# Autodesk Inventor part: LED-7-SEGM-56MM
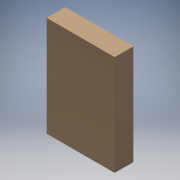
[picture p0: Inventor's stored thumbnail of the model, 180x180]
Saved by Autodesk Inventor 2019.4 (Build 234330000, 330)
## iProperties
Created: 2019-11
Part Number: LED-7-SEGM-56MM
Material: Generic
Document SubType Name: Modeling
Designer: Willist
Density: 1 g/cm^3
Appearance: MYTHT, LED-7-SEGM-56MM
Author: Willist
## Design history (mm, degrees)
sketch "MYTHT, LED-7-SEGM-56MM_63"
  geometry: L1 (-23.9, 34.85)-(23.4, 34.85); L2 (23.4, 34.85)-(23.4, -34.85); L3 (23.4, -34.85)-(-23.9, -34.85); L4 (-23.9, -34.85)-(-23.9, 34.85)
  constraints: 8 end point
extrude "Extrusion1" join sketch "MYTHT, LED-7-SEGM-56MM_63" distance "d0" = 1; taper "d1" = 0 deg
sketch "Sketch2"
  geometry: L1 (23.4, 34.85)-(-23.9, 34.85) reference; L2 (-23.9, -34.85)-(23.4, -34.85) reference; L3 (-23.9, 34.85)-(23.4, 34.85); L4 (23.4, 34.85)-(23.4, -34.85); L5 (23.4, -34.85)-(-23.9, -34.85); L6 (-23.9, -34.85)-(-23.9, 34.85); 1 further point
  constraints: 8 end point, 2 parallel, 1 horizontal, 1 perpendicular
extrude "Extrusion2" join sketch "Sketch2" distance "d2" = 11; taper "d3" = 0 deg
body "Solid1"
